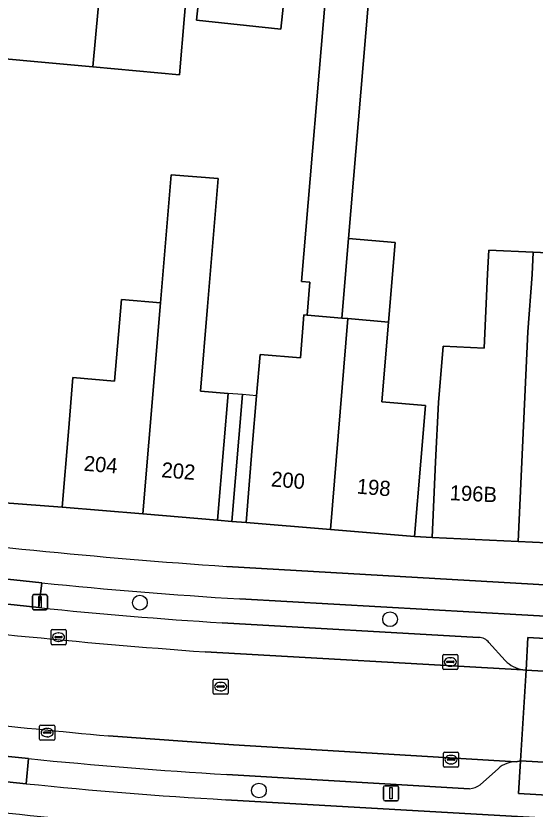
# Model space of a CAD drawing. Extents: x 158086 to 159499, y 382904 to 383981.
# Drawn here: x 158361.5 to 158395.9, y 383170.4 to 383222.9 of the extents above; entities that cross this region are included whole.
import ezdxf

# ---------------------------------------------------------------- set-up
doc = ezdxf.new("R2010")
doc.units = 0
for name, color, linetype in [('IMGEO_Berm_open', 7, 'Continuous'), ('IMGEO_Boom', 7, 'Continuous'), ('IMGEO_Erf', 7, 'Continuous'), ('IMGEO_Fietspad_gesloten', 7, 'Continuous'), ('IMGEO_Kolk', 7, 'Continuous'), ('IMGEO_Lichtmast', 7, 'Continuous'), ('IMGEO_Pand', 7, 'Continuous'), ('IMGEO_Pand_nummerreeks', 7, 'Continuous'), ('IMGEO_Pand_overbouw', 7, 'Continuous'), ('IMGEO_Parkeervlak_open', 7, 'Continuous'), ('IMGEO_Rijbaan_lokaal_gesloten', 7, 'Continuous'), ('IMGEO_Rijbaan_lokaal_open', 7, 'Continuous'), ('IMGEO_Rioolput', 7, 'Continuous'), ('IMGEO_Voetpad_open', 7, 'Continuous')]:
    doc.layers.add(name, color=color, linetype=linetype)

msp = doc.modelspace()

# ---------------------------------------------------------------- linework, layer by layer
at = {"layer": 'IMGEO_Berm_open'}
for points in [[(158363.247, 383185.397), (158363.052, 383183.761)], [(158410.395, 383179.363), (158410.542, 383182.413), (158376.349, 383184.334)], [(158375.168, 383182.758), (158392.142, 383181.785)], [(158395.059, 383179.659), (158395.283, 383179.629), (158395.396, 383181.784), (158409.102, 383180.989), (158409, 383178.829), (158409.185, 383178.843)], [(158392.825, 383181.454), (158393.901, 383180.259)], [(158362.367, 383173.783), (158362.215, 383172.123)], [(158394.908, 383173.625), (158394.63, 383173.578)], [(158408.915, 383172.819), (158408.705, 383172.834), (158408.565, 383170.681), (158394.778, 383171.471), (158394.908, 383173.625)], [(158393.445, 383173.124), (158392.24, 383172.058)], [(158391.544, 383171.79), (158375.482, 383172.731)], [(158375.415, 383171.065), (158464.529, 383165.969), (158487.406, 383164.364), (158487.539, 383166.035), (158474.588, 383166.996), (158454.152, 383168.258), (158411.587, 383170.678), (158411.239, 383170.841), (158410.146, 383172.145)]]:
    msp.add_lwpolyline(points, dxfattribs=at)
for centre, radius, start, end in [((158400.058, 383557.841), 374.259, 264.35535, 266.36785), ((158393.81, 383481.634), 299.457, 264.10453, 266.4308), ((158392.151, 383180.933), 0.852, 37.68, 90.6078), ((158395.359, 383181.655), 2.018, 223.761, 261.4585), ((158394.283, 383489.389), 317.215, 264.22561, 266.60224), ((158394.634, 383171.794), 1.784, 90.1313, 131.7946), ((158390.092, 383437.052), 266.392, 263.99322, 266.84168), ((158391.446, 383173.083), 1.297, 274.3455, 307.7736)]:
    msp.add_arc(centre, radius, start, end, dxfattribs=at)
at = {"layer": 'IMGEO_Boom'}
for centre in [(158369.734, 383184.089), (158386.285, 383182.995), (158377.607, 383171.673)]:
    msp.add_circle(centre, 0.489, dxfattribs=at)
at = {"layer": 'IMGEO_Erf'}
for points in [[(158373.01, 383226.839), (158372.354, 383218.991), (158366.626, 383219.514), (158357.166, 383220.377), (158356.532, 383213.421), (158347.391, 383214.254), (158348.025, 383221.211), (158346.812, 383221.322), (158347.878, 383230.272)], [(158379.506, 383226.176), (158379.067, 383222.012), (158373.477, 383222.6), (158373.916, 383226.764)], [(158359.325, 383190.797), (158364.587, 383190.404), (158365.004, 383195.387), (158365.303, 383198.966), (158368.064, 383198.735), (158368.516, 383204.134), (158371.094, 383203.918), (158371.801, 383212.38), (158374.913, 383212.119), (158374.206, 383203.658), (158373.739, 383198.073), (158375.57, 383197.92), (158375.286, 383194.527), (158374.869, 383189.544), (158375.812, 383189.466), (158376.755, 383189.387), (158377.172, 383194.37), (158377.456, 383197.763), (158377.685, 383200.499), (158380.352, 383200.276), (158380.59, 383203.109), (158380.803, 383203.091), (158380.986, 383205.27), (158380.432, 383205.316), (158382.167, 383225.973)], [(158385.005, 383225.706), (158383.532, 383208.166), (158386.627, 383207.907), (158386.187, 383202.64), (158385.746, 383197.365), (158388.634, 383197.123), (158388.326, 383193.436), (158387.909, 383188.453), (158389.063, 383188.399), (158389.295, 383193.394), (158389.477, 383197.329), (158389.784, 383201.041), (158392.508, 383200.915), (158392.736, 383205.834), (158392.808, 383207.388), (158395.753, 383207.251), (158398.123, 383207.141)]]:
    msp.add_lwpolyline(points, dxfattribs=at)
at = {"layer": 'IMGEO_Fietspad_gesloten'}
for points in [[(158469.526, 383181.066), (158375.483, 383186.486)], [(158356.84, 383186.093), (158363.247, 383185.397)], [(158376.349, 383184.334), (158410.542, 383182.413), (158417.046, 383182.047), (158459.444, 383179.637), (158474.658, 383178.653)], [(158362.215, 383172.123), (158356.246, 383172.732), (158354.48, 383172.941), (158353.257, 383173.086), (158348.056, 383173.715), (158347.422, 383173.791)], [(158494.317, 383163.738), (158487.406, 383164.364), (158464.529, 383165.969), (158375.415, 383171.065)]]:
    msp.add_lwpolyline(points, dxfattribs=at)
for centre, radius, start, end in [((158404.427, 383610.047), 424.549, 262.63593, 266.09078), ((158400.058, 383557.841), 374.259, 264.35535, 266.36785), ((158390.092, 383437.052), 266.392, 263.99322, 266.84168), ((158419.442, 383749.978), 582.74, 262.938629, 265.150545)]:
    msp.add_arc(centre, radius, start, end, dxfattribs=at)
at = {"layer": 'IMGEO_Kolk'}
for p, q in [((158363.932, 383182.313), (158364.784, 383182.313)), ((158363.857, 383181.387), (158363.857, 383182.239)), ((158364.116, 383181.807), (158364.116, 383181.819)), ((158364.554, 383181.77), (158364.156, 383181.77)), ((158364.159, 383181.856), (158364.557, 383181.856)), ((158364.345, 383182.093), (158364.37, 383182.093)), ((158364.6, 383181.819), (158364.6, 383181.807)), ((158364.858, 383182.239), (158364.858, 383181.387)), ((158364.784, 383181.313), (158363.932, 383181.313)), ((158364.368, 383181.533), (158364.343, 383181.533)), ((158389.84, 383180.67), (158390.692, 383180.67)), ((158389.765, 383179.744), (158389.765, 383180.596)), ((158390.024, 383180.164), (158390.024, 383180.176)), ((158390.067, 383180.213), (158390.465, 383180.213)), ((158390.253, 383180.45), (158390.278, 383180.45)), ((158390.508, 383180.176), (158390.508, 383180.164)), ((158390.766, 383180.596), (158390.766, 383179.744)), ((158390.692, 383179.67), (158389.84, 383179.67)), ((158390.462, 383180.127), (158390.064, 383180.127)), ((158390.276, 383179.89), (158390.251, 383179.89)), ((158363.178, 383176.001), (158364.03, 383176.001)), ((158363.103, 383175.075), (158363.103, 383175.927)), ((158363.362, 383175.495), (158363.362, 383175.507)), ((158363.8, 383175.458), (158363.402, 383175.458)), ((158363.405, 383175.544), (158363.803, 383175.544)), ((158363.591, 383175.781), (158363.616, 383175.781)), ((158363.846, 383175.507), (158363.846, 383175.495)), ((158364.104, 383175.927), (158364.104, 383175.075)), ((158364.03, 383175.001), (158363.178, 383175.001)), ((158363.614, 383175.221), (158363.589, 383175.221)), ((158389.814, 383173.29), (158389.814, 383174.142)), ((158389.889, 383174.216), (158390.741, 383174.216)), ((158390.302, 383173.996), (158390.327, 383173.996)), ((158390.815, 383174.142), (158390.815, 383173.29)), ((158390.073, 383173.71), (158390.073, 383173.722)), ((158390.511, 383173.673), (158390.113, 383173.673)), ((158390.116, 383173.759), (158390.514, 383173.759)), ((158390.325, 383173.436), (158390.3, 383173.436)), ((158390.557, 383173.722), (158390.557, 383173.71)), ((158390.741, 383173.216), (158389.889, 383173.216))]:
    msp.add_line(p, q, dxfattribs=at)
for points in [[(158363.932, 383182.313), (158364.784, 383182.313)], [(158363.857, 383181.387), (158363.857, 383182.239)], [(158364.858, 383182.239), (158364.858, 383181.387)], [(158364.784, 383181.313), (158363.932, 383181.313)], [(158389.84, 383180.67), (158390.692, 383180.67)], [(158389.765, 383179.744), (158389.765, 383180.596)], [(158390.766, 383180.596), (158390.766, 383179.744)], [(158390.692, 383179.67), (158389.84, 383179.67)], [(158363.178, 383176.001), (158364.03, 383176.001)], [(158363.103, 383175.075), (158363.103, 383175.927)], [(158364.104, 383175.927), (158364.104, 383175.075)], [(158364.03, 383175.001), (158363.178, 383175.001)], [(158389.814, 383173.29), (158389.814, 383174.142)], [(158389.889, 383174.216), (158390.741, 383174.216)], [(158390.815, 383174.142), (158390.815, 383173.29)], [(158390.741, 383173.216), (158389.889, 383173.216)]]:
    msp.add_lwpolyline(points, dxfattribs=at)
for centre, radius, start, end in [((158363.934, 383182.237), 0.0765, 91.552, 178.448), ((158363.934, 383182.237), 0.0765, 91.552, 178.448), ((158364.782, 383182.237), 0.0765, 1.552, 88.448), ((158364.782, 383182.237), 0.0765, 1.552, 88.448), ((158364.156, 383181.816), 0.0403, 85.8775, 175.7526), ((158364.153, 383181.806), 0.0366, 178.938, 274.7102), ((158364.557, 383181.813), 0.043, 264.8664, 352.4533), ((158364.561, 383181.818), 0.0386, 1.7309, 96.639), ((158363.934, 383181.389), 0.0765, 181.552, 268.448), ((158363.934, 383181.389), 0.0765, 181.552, 268.448), ((158364.782, 383181.389), 0.0765, 271.552, 358.448), ((158364.782, 383181.389), 0.0765, 271.552, 358.448), ((158389.842, 383180.594), 0.0765, 91.552, 178.448), ((158389.842, 383180.594), 0.0765, 91.552, 178.448), ((158390.69, 383180.594), 0.0765, 1.552, 88.448), ((158390.69, 383180.594), 0.0765, 1.552, 88.448), ((158390.064, 383180.173), 0.0403, 85.8775, 175.7526), ((158390.061, 383180.163), 0.0366, 178.938, 274.7102), ((158390.465, 383180.17), 0.043, 264.8664, 352.4533), ((158390.469, 383180.175), 0.0386, 1.7309, 96.639), ((158389.842, 383179.746), 0.0765, 181.552, 268.448), ((158389.842, 383179.746), 0.0765, 181.552, 268.448), ((158390.69, 383179.746), 0.0765, 271.552, 358.448), ((158390.69, 383179.746), 0.0765, 271.552, 358.448), ((158363.18, 383175.925), 0.0765, 91.552, 178.448), ((158363.18, 383175.925), 0.0765, 91.552, 178.448), ((158364.028, 383175.925), 0.0765, 1.552, 88.448), ((158364.028, 383175.925), 0.0765, 1.552, 88.448), ((158363.402, 383175.504), 0.0403, 85.8775, 175.7526), ((158363.399, 383175.494), 0.0366, 178.938, 274.7102), ((158363.803, 383175.501), 0.043, 264.8664, 352.4533), ((158363.807, 383175.506), 0.0386, 1.7309, 96.639), ((158363.18, 383175.077), 0.0765, 181.552, 268.448), ((158363.18, 383175.077), 0.0765, 181.552, 268.448), ((158364.028, 383175.077), 0.0765, 271.552, 358.448), ((158364.028, 383175.077), 0.0765, 271.552, 358.448), ((158389.891, 383174.14), 0.0765, 91.552, 178.448), ((158389.891, 383174.14), 0.0765, 91.552, 178.448), ((158390.739, 383174.14), 0.0765, 1.552, 88.448), ((158390.739, 383174.14), 0.0765, 1.552, 88.448), ((158390.113, 383173.719), 0.0403, 85.8775, 175.7526), ((158390.11, 383173.709), 0.0366, 178.938, 274.7102), ((158390.514, 383173.716), 0.043, 264.8664, 352.4533), ((158390.518, 383173.721), 0.0386, 1.7309, 96.639), ((158389.891, 383173.292), 0.0765, 181.552, 268.448), ((158389.891, 383173.292), 0.0765, 181.552, 268.448), ((158390.739, 383173.292), 0.0765, 271.552, 358.448), ((158390.739, 383173.292), 0.0765, 271.552, 358.448)]:
    msp.add_arc(centre, radius, start, end, dxfattribs=at)
for centre, major_axis, ratio, start_param, end_param in [((158364.344, 383181.813), (-0.387, 0.002), 0.722429, 4.712389, 7.853982), ((158364.369, 383181.813), (-0.39, 0.002), 0.717154, 1.570796, 4.712389), ((158390.252, 383180.17), (-0.387, 0.002), 0.722429, 4.712389, 7.853982), ((158390.277, 383180.17), (-0.39, 0.002), 0.717154, 1.570796, 4.712389), ((158363.59, 383175.501), (-0.387, 0.002), 0.722429, 4.712389, 7.853982), ((158363.615, 383175.501), (-0.39, 0.002), 0.717154, 1.570796, 4.712389), ((158390.301, 383173.716), (-0.387, 0.002), 0.722429, 4.712389, 7.853982), ((158390.326, 383173.716), (-0.39, 0.002), 0.717154, 1.570796, 4.712389)]:
    msp.add_ellipse(centre, major_axis=major_axis, ratio=ratio, start_param=start_param, end_param=end_param, dxfattribs=at)
at = {"layer": 'IMGEO_Lichtmast'}
for p, q in [((158362.63, 383183.723), (158362.63, 383184.523)), ((158362.63, 383184.523), (158362.63, 383183.723)), ((158362.73, 383184.623), (158363.52, 383184.623)), ((158363.52, 383184.623), (158362.73, 383184.623)), ((158363.62, 383184.523), (158363.62, 383183.723)), ((158363.62, 383183.723), (158363.62, 383184.523)), ((158363.52, 383183.623), (158362.73, 383183.623)), ((158362.73, 383183.623), (158363.52, 383183.623)), ((158385.852, 383171.089), (158385.852, 383171.889)), ((158385.852, 383171.889), (158385.852, 383171.089)), ((158385.952, 383171.989), (158386.742, 383171.989)), ((158386.742, 383171.989), (158385.952, 383171.989)), ((158386.842, 383171.889), (158386.842, 383171.089)), ((158386.842, 383171.089), (158386.842, 383171.889)), ((158386.742, 383170.989), (158385.952, 383170.989)), ((158385.952, 383170.989), (158386.742, 383170.989))]:
    msp.add_line(p, q, dxfattribs=at)
for points in [[(158363.05, 383184.498), (158363.2, 383184.498), (158363.2, 383183.748), (158363.05, 383183.748), (158363.05, 383184.498)], [(158386.272, 383171.864), (158386.422, 383171.864), (158386.422, 383171.114), (158386.272, 383171.114), (158386.272, 383171.864)]]:
    msp.add_lwpolyline(points, dxfattribs=at)
for centre, start, end in [((158362.73, 383184.523), 90, 180), ((158362.73, 383184.523), 90, 180), ((158363.52, 383184.523), 0, 90), ((158363.52, 383184.523), 360, 90), ((158362.73, 383183.723), 180, 270), ((158362.73, 383183.723), 180, 270), ((158363.52, 383183.723), 270, 0), ((158363.52, 383183.723), 270, 0), ((158385.952, 383171.889), 90, 180), ((158385.952, 383171.889), 90, 180), ((158386.742, 383171.889), 0, 90), ((158386.742, 383171.889), 360, 90), ((158385.952, 383171.089), 180, 270), ((158385.952, 383171.089), 180, 270), ((158386.742, 383171.089), 270, 0), ((158386.742, 383171.089), 270, 0)]:
    msp.add_arc(centre, 0.1, start, end, dxfattribs=at)
at = {"layer": 'IMGEO_Pand'}
for points in [[(158367.915, 383233.64), (158362.11, 383234.317), (158356.147, 383235.013), (158349.616, 383235.775), (158348.549, 383235.903), (158348.524, 383235.697), (158348.452, 383235.089), (158347.878, 383230.272), (158346.812, 383221.322), (158348.025, 383221.211), (158357.166, 383220.377), (158366.626, 383219.514), (158367.349, 383227.435)], [(158373.01, 383226.839), (158367.349, 383227.435), (158366.626, 383219.514), (158372.354, 383218.991)], [(158379.506, 383226.176), (158373.916, 383226.764), (158373.477, 383222.6), (158379.067, 383222.012)], [(158385.005, 383225.706), (158382.167, 383225.973), (158380.432, 383205.316), (158380.986, 383205.27), (158380.803, 383203.091), (158383.089, 383202.9), (158383.532, 383208.166)], [(158375.57, 383197.92), (158373.739, 383198.073), (158374.206, 383203.658), (158374.913, 383212.119), (158371.801, 383212.38), (158371.094, 383203.918), (158369.927, 383189.957), (158374.869, 383189.544), (158375.286, 383194.527)], [(158383.532, 383208.166), (158383.089, 383202.9), (158383.495, 383202.866), (158386.187, 383202.64), (158386.627, 383207.907)], [(158395.753, 383207.251), (158392.808, 383207.388), (158392.736, 383205.834), (158392.508, 383200.915), (158389.784, 383201.041), (158389.477, 383197.329), (158389.295, 383193.394), (158389.063, 383188.399), (158394.755, 383188.135), (158395.4, 383201.987), (158395.685, 383205.777)], [(158395.753, 383207.251), (158395.685, 383205.777), (158395.4, 383201.987), (158394.755, 383188.135), (158400.444, 383187.871), (158400.676, 383192.866), (158400.861, 383196.853), (158398.044, 383196.984), (158398.282, 383202.111), (158397.891, 383202.129), (158398.058, 383205.732), (158398.123, 383207.141)], [(158369.927, 383189.957), (158371.094, 383203.918), (158368.516, 383204.134), (158368.064, 383198.735), (158365.303, 383198.966), (158365.004, 383195.387), (158364.587, 383190.404)], [(158383.495, 383202.866), (158383.089, 383202.9), (158380.803, 383203.091), (158380.59, 383203.109), (158380.352, 383200.276), (158377.685, 383200.499), (158377.456, 383197.763), (158377.172, 383194.37), (158376.755, 383189.387), (158382.332, 383188.92)], [(158383.495, 383202.866), (158382.332, 383188.92), (158387.909, 383188.453), (158388.326, 383193.436), (158388.634, 383197.123), (158385.746, 383197.365), (158386.187, 383202.64)]]:
    msp.add_lwpolyline(points, close=True, dxfattribs=at)
at = {"layer": 'IMGEO_Pand_overbouw'}
for points in [[(158375.57, 383197.92), (158375.286, 383194.527), (158374.869, 383189.544), (158375.812, 383189.466), (158376.513, 383197.842)], [(158377.456, 383197.763), (158376.513, 383197.842), (158375.812, 383189.466), (158376.755, 383189.387), (158377.172, 383194.37)]]:
    msp.add_lwpolyline(points, close=True, dxfattribs=at)
at = {"layer": 'IMGEO_Parkeervlak_open'}
for points in [[(158363.052, 383183.761), (158356.68, 383184.444), (158351.695, 383185.014), (158349.522, 383185.279)], [(158392.142, 383181.785), (158375.168, 383182.758)], [(158393.901, 383180.259), (158392.825, 383181.454)], [(158374.061, 383180.835), (158395.059, 383179.659)], [(158347.58, 383175.407), (158348.254, 383175.33), (158353.456, 383174.734), (158354.676, 383174.588), (158356.377, 383174.385), (158362.367, 383173.783)], [(158394.63, 383173.578), (158375.931, 383174.69), (158367.67, 383175.281)], [(158392.24, 383172.058), (158393.445, 383173.124)], [(158375.482, 383172.731), (158391.544, 383171.79)]]:
    msp.add_lwpolyline(points, dxfattribs=at)
for points in [[(158395.283, 383179.629), (158409, 383178.829), (158409.102, 383180.989), (158395.396, 383181.784)], [(158394.908, 383173.625), (158394.778, 383171.471), (158408.565, 383170.681), (158408.705, 383172.834)]]:
    msp.add_lwpolyline(points, close=True, dxfattribs=at)
for centre, radius, start, end in [((158409.387, 383662.379), 482.838, 262.84682, 265.80428), ((158393.81, 383481.634), 299.457, 264.10453, 266.4308), ((158392.151, 383180.933), 0.852, 37.68, 90.6078), ((158395.359, 383181.655), 2.018, 223.761, 261.4585), ((158423.239, 383776.404), 603.686, 262.888599, 264.718506), ((158394.283, 383489.389), 317.215, 264.22561, 266.60224), ((158394.634, 383171.794), 1.784, 90.1313, 131.7946), ((158391.446, 383173.083), 1.297, 274.3455, 307.7736)]:
    msp.add_arc(centre, radius, start, end, dxfattribs=at)
at = {"layer": 'IMGEO_Rijbaan_lokaal_gesloten'}
msp.add_lwpolyline([(158367.67, 383175.281), (158375.931, 383174.69), (158394.63, 383173.578), (158394.908, 383173.625), (158395.283, 383179.629), (158395.059, 383179.659), (158374.061, 383180.835)], dxfattribs=at)
for centre, radius, start, end in [((158409.387, 383662.379), 482.838, 262.84682, 265.80428), ((158423.239, 383776.404), 603.686, 262.888599, 264.718506)]:
    msp.add_arc(centre, radius, start, end, dxfattribs=at)
at = {"layer": 'IMGEO_Rijbaan_lokaal_open'}
msp.add_lwpolyline([(158395.283, 383179.629), (158394.908, 383173.625), (158408.705, 383172.834), (158409, 383178.829)], close=True, dxfattribs=at)
at = {"layer": 'IMGEO_Rioolput'}
for p, q in [((158374.574, 383178.116), (158374.574, 383178.968)), ((158374.649, 383179.042), (158375.501, 383179.042)), ((158374.876, 383178.585), (158375.274, 383178.585)), ((158375.062, 383178.822), (158375.087, 383178.822)), ((158375.575, 383178.968), (158375.575, 383178.116)), ((158374.833, 383178.536), (158374.833, 383178.548)), ((158375.271, 383178.499), (158374.873, 383178.499)), ((158375.085, 383178.262), (158375.06, 383178.262)), ((158375.317, 383178.548), (158375.317, 383178.536)), ((158375.501, 383178.042), (158374.649, 383178.042))]:
    msp.add_line(p, q, dxfattribs=at)
for points in [[(158374.574, 383178.116), (158374.574, 383178.968)], [(158374.649, 383179.042), (158375.501, 383179.042)], [(158375.575, 383178.968), (158375.575, 383178.116)], [(158375.501, 383178.042), (158374.649, 383178.042)]]:
    msp.add_lwpolyline(points, dxfattribs=at)
for centre, radius, start, end in [((158374.651, 383178.966), 0.0765, 91.552, 178.448), ((158374.651, 383178.966), 0.0765, 91.552, 178.448), ((158374.873, 383178.545), 0.0403, 85.8775, 175.7526), ((158375.278, 383178.547), 0.0386, 1.7309, 96.639), ((158375.499, 383178.966), 0.0765, 1.552, 88.448), ((158375.499, 383178.966), 0.0765, 1.552, 88.448), ((158374.651, 383178.118), 0.0765, 181.552, 268.448), ((158374.651, 383178.118), 0.0765, 181.552, 268.448), ((158374.87, 383178.535), 0.0366, 178.938, 274.7102), ((158375.274, 383178.542), 0.043, 264.8664, 352.4533), ((158375.499, 383178.118), 0.0765, 271.552, 358.448), ((158375.499, 383178.118), 0.0765, 271.552, 358.448)]:
    msp.add_arc(centre, radius, start, end, dxfattribs=at)
for centre, major_axis, ratio, start_param, end_param in [((158375.061, 383178.542), (-0.387, 0.002), 0.722429, 4.712389, 7.853982), ((158375.086, 383178.542), (-0.39, 0.002), 0.717154, 1.570796, 4.712389)]:
    msp.add_ellipse(centre, major_axis=major_axis, ratio=ratio, start_param=start_param, end_param=end_param, dxfattribs=at)
at = {"layer": 'IMGEO_Voetpad_open'}
for points in [[(158400.444, 383187.871), (158394.755, 383188.135), (158389.063, 383188.399), (158387.909, 383188.453), (158382.332, 383188.92), (158376.755, 383189.387), (158375.812, 383189.466), (158374.869, 383189.544), (158369.927, 383189.957), (158364.587, 383190.404), (158359.325, 383190.797), (158354.028, 383191.594), (158350.422, 383192.137), (158346.007, 383192.801), (158345.544, 383192.823), (158339.742, 383193.696), (158333.428, 383194.647), (158327.023, 383195.611), (158324.318, 383196.231), (158318.089, 383197.403), (158312.044, 383198.541)], [(158375.483, 383186.486), (158469.526, 383181.066)]]:
    msp.add_lwpolyline(points, dxfattribs=at)
for points in [[(158356.68, 383184.444), (158363.052, 383183.761), (158363.247, 383185.397), (158356.84, 383186.093)], [(158362.367, 383173.783), (158356.377, 383174.385), (158356.246, 383172.732), (158362.215, 383172.123)]]:
    msp.add_lwpolyline(points, close=True, dxfattribs=at)
for centre, radius, start, end in [((158404.427, 383610.047), 424.549, 262.63593, 266.09078), ((158419.442, 383749.978), 582.74, 262.938629, 265.150545)]:
    msp.add_arc(centre, radius, start, end, dxfattribs=at)

# ---------------------------------------------------------------- texts
at = {"layer": 'IMGEO_Pand_nummerreeks'}
for s, rotation, p in [('204', 355.2188, (158365.994, 383192.815)), ('202', 355.2215, (158371.133, 383192.385)), ('200', 355.2158, (158378.383, 383191.779)), ('198', 355.2134, (158384.051, 383191.304)), ('196B', 357.3472, (158390.211, 383190.868))]:
    msp.add_text(s, height=1, rotation=rotation, dxfattribs=at).set_placement(p)

doc.saveas('drawing.dxf')
